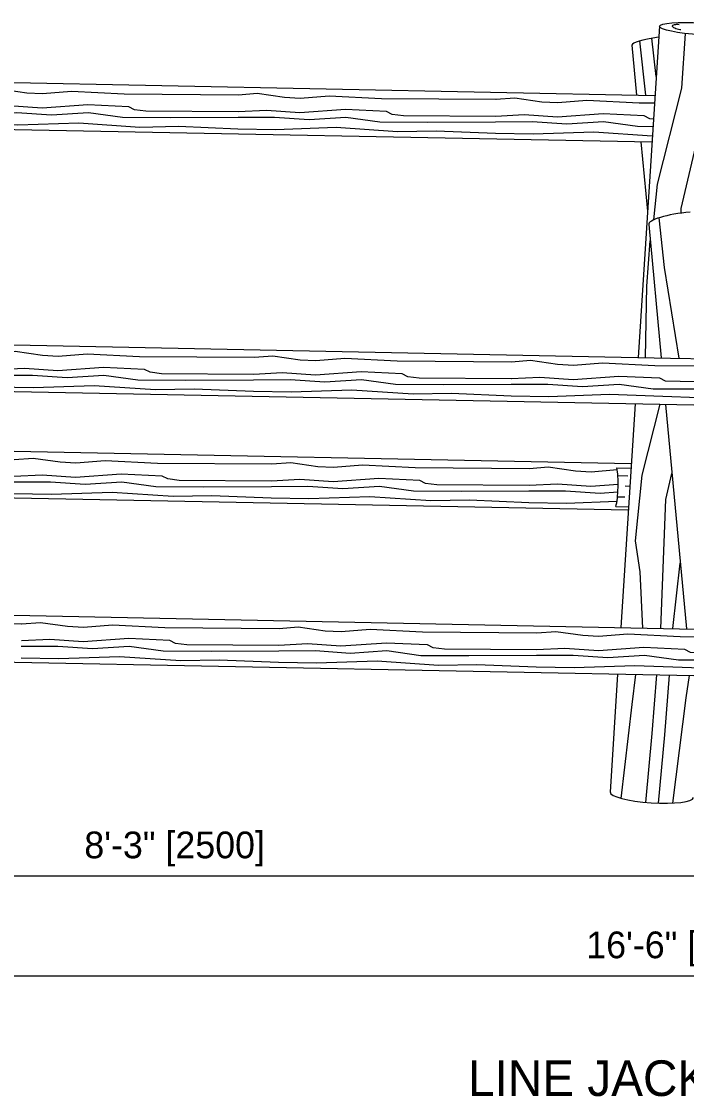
# Model space of a CAD drawing. Extents: x 49991.4 to 50021, y 49987.6 to 50011.4.
# Drawn here: x 50010.615 to 50012.107, y 49994.539 to 49996.952 of the extents above; entities that cross this region are included whole.
import ezdxf

# ---------------------------------------------------------------- set-up
doc = ezdxf.new("R2010")
doc.units = 0
for name, color, linetype in [('Level 1', 7, 'Continuous'), ('Level 2', 7, 'Continuous'), ('Level 3', 7, 'Continuous')]:
    doc.layers.add(name, color=color, linetype=linetype)

msp = doc.modelspace()

# ---------------------------------------------------------------- linework, layer by layer
at = {"layer": 'Level 1'}
for p, q in [((50012.0463, 49996.941), (50011.9985, 49996.1979)), ((50011.9848, 49996.8988), (50011.9953, 49996.7863)), ((50009.9419, 49996.828), (50012.0363, 49996.7855)), ((50009.9351, 49996.7224), (50012.0296, 49996.6814)), ((50012.005, 49996.6819), (50012.0195, 49996.5257)), ((50012.0224, 49996.4959), (50012.0502, 49996.1968)), ((50009.789, 49996.2427), (50012.0713, 49996.1964)), ((50012.0713, 49996.1964), (50014.3767, 49996.1497)), ((50009.7813, 49996.137), (50012.2525, 49996.0886)), ((50011.9918, 49996.0937), (50011.9595, 49995.5914)), ((50012.06, 49996.0924), (50012.1069, 49995.5884)), ((50009.9717, 49996.0004), (50011.9831, 49995.9596)), ((50011.9509, 49995.9499), (50011.9825, 49995.9493)), ((50011.953, 49995.9327), (50011.9758, 49995.9318)), ((50011.9698, 49995.9092), (50011.9799, 49995.9087)), ((50010.0861, 49995.8924), (50011.9764, 49995.8554)), ((50011.9523, 49995.8851), (50011.9687, 49995.8851)), ((50011.9488, 49995.8631), (50011.9769, 49995.8625)), ((50009.8457, 49995.6343), (50012.128, 49995.588)), ((50009.838, 49995.5286), (50012.3092, 49995.4802)), ((50011.9527, 49995.4872), (50011.9357, 49995.2223))]:
    msp.add_line(p, q, dxfattribs=at)
for points in [[(50012.039, 49996.828), (50012.0297, 49996.914)], [(50012.0339, 49996.5066), (50012.042, 49996.5868), (50012.0969, 49996.8019), (50012.1048, 49996.9247)], [(50012.095, 49996.5216), (50012.0953, 49996.5317), (50012.157, 49996.7957), (50012.1651, 49996.9206)], [(50012.0159, 49996.786), (50012.0026, 49996.9079)], [(50011.1019, 49996.7864), (50010.8453, 49996.7885), (50010.7278, 49996.7944), (50010.6625, 49996.7891), (50010.6271, 49996.791), (50010.5663, 49996.7998), (50010.5239, 49996.7965)], [(50011.6798, 49996.7763), (50011.4232, 49996.7784), (50011.3057, 49996.7843), (50011.2404, 49996.779), (50011.205, 49996.7809), (50011.1442, 49996.7897), (50011.1019, 49996.7864)], [(50011.1012, 49996.7487), (50010.8942, 49996.7504), (50010.8688, 49996.7534), (50010.8562, 49996.76), (50010.7642, 49996.7643), (50010.6619, 49996.757), (50010.5869, 49996.7621), (50010.5232, 49996.7588)], [(50012.0352, 49996.7681), (50012.0011, 49996.7683), (50011.8836, 49996.7742), (50011.8183, 49996.7689), (50011.7829, 49996.7708), (50011.7221, 49996.7796), (50011.6797, 49996.7763)], [(50011.101, 49996.736), (50010.9493, 49996.7353), (50010.8416, 49996.7359), (50010.7653, 49996.7464), (50010.6829, 49996.7412), (50010.605, 49996.7464), (50010.523, 49996.7461)], [(50011.6792, 49996.7387), (50011.4722, 49996.7403), (50011.4468, 49996.7433), (50011.4341, 49996.75), (50011.3422, 49996.7542), (50011.2399, 49996.7469), (50011.1648, 49996.7521), (50011.1012, 49996.7487)], [(50012.0329, 49996.7323), (50012.0246, 49996.7332), (50012.012, 49996.7399), (50011.9201, 49996.7441), (50011.8178, 49996.7369), (50011.7427, 49996.742), (50011.6791, 49996.7387)], [(50011.1005, 49996.7103), (50010.9673, 49996.7157), (50010.8809, 49996.7141), (50010.7436, 49996.7235), (50010.6074, 49996.7189), (50010.5226, 49996.7203)], [(50011.6789, 49996.726), (50011.5272, 49996.7252), (50011.4195, 49996.7258), (50011.3432, 49996.7364), (50011.2608, 49996.7311), (50011.1829, 49996.7364), (50011.101, 49996.736)], [(50012.0318, 49996.7155), (50011.9974, 49996.7157), (50011.9211, 49996.7263), (50011.8388, 49996.7211), (50011.7609, 49996.7263), (50011.6789, 49996.726)], [(50011.6784, 49996.7002), (50011.5453, 49996.7057), (50011.4588, 49996.704), (50011.3215, 49996.7134), (50011.1853, 49996.7088), (50011.1005, 49996.7103)], [(50012.0304, 49996.6944), (50011.8994, 49996.7033), (50011.7632, 49996.6987), (50011.6784, 49996.7002)], [(50012.0906, 49996.196), (50012.0579, 49996.3995), (50012.0458, 49996.5111)], [(50012.0178, 49996.3575), (50012.0258, 49996.4595)], [(50012.0155, 49996.1975), (50012.0178, 49996.3575)], [(50011.1369, 49996.1973), (50010.8803, 49996.1994), (50010.7628, 49996.2053), (50010.6975, 49996.2), (50010.6621, 49996.2019), (50010.6013, 49996.2107), (50010.5589, 49996.2074)], [(50011.7148, 49996.1872), (50011.4583, 49996.1893), (50011.3407, 49996.1952), (50011.2755, 49996.1899), (50011.2401, 49996.1918), (50011.1793, 49996.2006), (50011.1369, 49996.1973)], [(50012.2583, 49996.1774), (50012.0362, 49996.1792), (50011.9186, 49996.1851), (50011.8534, 49996.1798), (50011.818, 49996.1817), (50011.7572, 49996.1905), (50011.7148, 49996.1872)], [(50011.1362, 49996.1596), (50010.9293, 49996.1612), (50010.9038, 49996.1643), (50010.8912, 49996.1709), (50010.7993, 49996.1752), (50010.6969, 49996.1679), (50010.6219, 49996.173), (50010.5583, 49996.1697)], [(50011.7142, 49996.1496), (50011.5072, 49996.1512), (50011.4818, 49996.1542), (50011.4691, 49996.1609), (50011.3772, 49996.1651), (50011.2749, 49996.1578), (50011.1999, 49996.163), (50011.1362, 49996.1596)], [(50011.136, 49996.1469), (50010.9843, 49996.1462), (50010.8766, 49996.1468), (50010.8003, 49996.1573), (50010.7179, 49996.1521), (50010.6401, 49996.1573), (50010.5581, 49996.157)], [(50011.7139, 49996.1369), (50011.5622, 49996.1361), (50011.4545, 49996.1367), (50011.3782, 49996.1473), (50011.2959, 49996.142), (50011.218, 49996.1473), (50011.136, 49996.1469)], [(50012.0668, 49996.1264), (50012.0324, 49996.1266), (50011.9562, 49996.1372), (50011.8738, 49996.1319), (50011.7959, 49996.1372), (50011.7139, 49996.1369)], [(50012.2559, 49996.1398), (50012.0597, 49996.1441), (50012.047, 49996.1508), (50011.9551, 49996.155), (50011.8528, 49996.1477), (50011.7778, 49996.1529), (50011.7141, 49996.1496)], [(50011.1355, 49996.1211), (50011.0024, 49996.1266), (50010.9159, 49996.125), (50010.7786, 49996.1343), (50010.6424, 49996.1297), (50010.5576, 49996.1312)], [(50011.7135, 49996.1111), (50011.5803, 49996.1165), (50011.4938, 49996.1149), (50011.3565, 49996.1243), (50011.2203, 49996.1197), (50011.1355, 49996.1211)], [(50012.2534, 49996.1025), (50011.9344, 49996.1142), (50011.7982, 49996.1096), (50011.7135, 49996.1111)], [(50012.2918, 49996.1268), (50012.0668, 49996.1264)], [(50012.0095, 49995.5904), (50012.0029, 49995.7166), (50011.9925, 49995.7863), (50012.0076, 49995.9338), (50012.0481, 49996.0926)], [(50011.1768, 49995.9579), (50010.9202, 49995.96), (50010.8027, 49995.9659), (50010.7374, 49995.9606), (50010.702, 49995.9625), (50010.6412, 49995.9712), (50010.5988, 49995.968)], [(50011.7547, 49995.9478), (50011.4982, 49995.9499), (50011.3806, 49995.9558), (50011.3154, 49995.9505), (50011.28, 49995.9524), (50011.2192, 49995.9612), (50011.1768, 49995.9579)], [(50011.9517, 49995.9451), (50011.8933, 49995.9404), (50011.8579, 49995.9423), (50011.7971, 49995.9511), (50011.7547, 49995.9478)], [(50011.1761, 49995.9202), (50010.9692, 49995.9218), (50010.9437, 49995.9249), (50010.9311, 49995.9315), (50010.8392, 49995.9358), (50010.7368, 49995.9285), (50010.6618, 49995.9336), (50010.5982, 49995.9303)], [(50011.7541, 49995.9101), (50011.5471, 49995.9118), (50011.5217, 49995.9148), (50011.509, 49995.9214), (50011.4171, 49995.9257), (50011.3148, 49995.9184), (50011.2398, 49995.9235), (50011.1761, 49995.9202)], [(50012.0499, 49995.5896), (50012.0609, 49995.8788), (50012.0745, 49995.9369)], [(50011.1754, 49995.8817), (50011.0423, 49995.8872), (50010.9558, 49995.8856), (50010.8185, 49995.8949), (50010.6823, 49995.8903), (50010.5975, 49995.8918)], [(50011.1759, 49995.9075), (50011.0242, 49995.9068), (50010.9165, 49995.9073), (50010.8402, 49995.9179), (50010.7579, 49995.9127), (50010.68, 49995.9179), (50010.598, 49995.9176)], [(50011.7538, 49995.8974), (50011.6022, 49995.8967), (50011.4944, 49995.8973), (50011.4181, 49995.9078), (50011.3358, 49995.9026), (50011.2579, 49995.9078), (50011.1759, 49995.9075)], [(50011.9531, 49995.895), (50011.9137, 49995.8925), (50011.8358, 49995.8978), (50011.7538, 49995.8974)], [(50011.9537, 49995.9127), (50011.8927, 49995.9083), (50011.8177, 49995.9135), (50011.754, 49995.9101)], [(50011.7534, 49995.8717), (50011.6202, 49995.8771), (50011.5337, 49995.8755), (50011.3964, 49995.8849), (50011.2602, 49995.8803), (50011.1754, 49995.8817)], [(50011.951, 49995.874), (50011.8381, 49995.8702), (50011.7534, 49995.8717)], [(50012.0763, 49995.5891), (50012.0932, 49995.7356)], [(50010.6157, 49995.599), (50010.3591, 49995.6011), (50010.2416, 49995.6069), (50010.1763, 49995.6016), (50010.1409, 49995.6036), (50010.0801, 49995.6123), (50010.0322, 49995.6086)], [(50011.1936, 49995.5889), (50010.937, 49995.591), (50010.8195, 49995.5969), (50010.7542, 49995.5916), (50010.7188, 49995.5935), (50010.658, 49995.6023), (50010.6156, 49995.599)], [(50011.7715, 49995.5788), (50011.515, 49995.5809), (50011.3974, 49995.5868), (50011.3322, 49995.5815), (50011.2968, 49995.5834), (50011.236, 49995.5922), (50011.1936, 49995.5889)], [(50012.315, 49995.5691), (50012.0929, 49995.5708), (50011.9753, 49995.5767), (50011.91, 49995.5714), (50011.8746, 49995.5733), (50011.8138, 49995.5821), (50011.7715, 49995.5788)], [(50011.1929, 49995.5512), (50010.986, 49995.5529), (50010.9605, 49995.5559), (50010.9479, 49995.5625), (50010.856, 49995.5668), (50010.7536, 49995.5595), (50010.6786, 49995.5646), (50010.615, 49995.5613)], [(50011.1927, 49995.5385), (50011.041, 49995.5378), (50010.9333, 49995.5384), (50010.857, 49995.5489), (50010.7746, 49995.5437), (50010.6967, 49995.5489), (50010.6148, 49995.5486)], [(50011.7706, 49995.5285), (50011.6189, 49995.5277), (50011.5112, 49995.5283), (50011.4349, 49995.5389), (50011.3526, 49995.5336), (50011.2747, 49995.5389), (50011.1927, 49995.5385)], [(50011.7709, 49995.5412), (50011.5639, 49995.5428), (50011.5385, 49995.5458), (50011.5258, 49995.5525), (50011.4339, 49995.5567), (50011.3316, 49995.5494), (50011.2566, 49995.5546), (50011.1929, 49995.5512)], [(50012.3126, 49995.5314), (50012.1164, 49995.5357), (50012.1037, 49995.5424), (50012.0118, 49995.5466), (50011.9095, 49995.5394), (50011.8345, 49995.5445), (50011.7708, 49995.5412)], [(50011.1922, 49995.5128), (50011.0591, 49995.5182), (50010.9726, 49995.5166), (50010.8353, 49995.526), (50010.6991, 49995.5213), (50010.6143, 49995.5228)], [(50011.7702, 49995.5027), (50011.637, 49995.5081), (50011.5505, 49995.5065), (50011.4132, 49995.5159), (50011.277, 49995.5113), (50011.1922, 49995.5128)], [(50012.1235, 49995.518), (50012.0891, 49995.5182), (50012.0129, 49995.5288), (50011.9305, 49995.5236), (50011.8526, 49995.5288), (50011.7706, 49995.5285)], [(50012.3101, 49995.4942), (50011.9911, 49995.5058), (50011.8549, 49995.5012), (50011.7702, 49995.5027)], [(50011.9608, 49995.2081), (50011.9856, 49995.4189), (50011.9935, 49995.4864)], [(50012.016, 49995.199), (50012.0301, 49995.3535), (50012.0405, 49995.4854)], [(50012.0445, 49995.1973), (50012.0585, 49995.3506), (50012.0691, 49995.4849)], [(50012.0768, 49995.1975), (50012.1066, 49995.4338), (50012.1136, 49995.484)]]:
    msp.add_lwpolyline(points, dxfattribs=at)
msp.add_ellipse((50012.1401, 49996.9351), major_axis=(0.0937, -0.0058), ratio=0.143064, dxfattribs=at)
for centre, major_axis, ratio, start_param, end_param in [((50012.0782, 49996.9086), (-0.0934, -0.0097), 0.126327, 5.066199, 6.283302), ((50012.1158, 49996.505), (0.0934, 0.0089), 0.201542, 1.555621, 3.157543), ((50011.9448, 49995.9073), (0.0011, 0.053), 0.166587, 3.729315, 5.649064), ((50012.0294, 49995.2163), (-0.0937, 0.0061), 0.194104, 0.000064, 3.132664)]:
    msp.add_ellipse(centre, major_axis=major_axis, ratio=ratio, start_param=start_param, end_param=end_param, dxfattribs=at)
msp.add_spline([(50012.0947, 49996.9327), (50012.0892, 49996.9338), (50012.0834, 49996.9352), (50012.0791, 49996.9378), (50012.0761, 49996.9405), (50012.0766, 49996.9437), (50012.0806, 49996.9446), (50012.085, 49996.9455), (50012.0909, 49996.9452)], degree=3, dxfattribs=at)
at = {"layer": 'Level 3'}
for p, q in [((50012.2382, 49995.0336), (50009.9521, 49995.0336)), ((50014.5466, 49994.8093), (50009.9521, 49994.8093))]:
    msp.add_line(p, q, dxfattribs=at)

# ---------------------------------------------------------------- texts
at = {"layer": 'Level 2'}
for s, p in [('8\'-3" [2500]', (50010.7562, 49995.0736)), ('16\'-6" [5000]', (50011.8823, 49994.8493))]:
    msp.add_text(s, height=0.06, rotation=0, dxfattribs=at).set_placement(p)
msp.add_text('LINE JACK SPACING', height=0.08, dxfattribs=at).set_placement((50011.6172, 49994.5401))

doc.saveas('drawing.dxf')
